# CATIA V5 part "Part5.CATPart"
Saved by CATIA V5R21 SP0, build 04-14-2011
Part number: Part5
Bounding box of the stored display mesh (mm): x 0 to 0, y -30 to 30, z -30 to 30
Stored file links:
  C:\Users\RIAD MAHAMUD PIASH\Desktop\Part5.CATPart
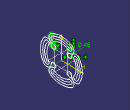
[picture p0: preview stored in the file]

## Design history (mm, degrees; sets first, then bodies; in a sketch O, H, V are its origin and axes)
Body1 (main body)
  Sketch1 on yz-plane, origin (0, 0, 0), H (0, 1, 0), V (0, 0, 1)
    construction circle A1 centre (0, 0) radius 24
    arc A2 centre (0, 0) radius 24 from (12, 20.7846) to (-12, 20.7846) ccw
    point P1 (12, 20.7846)
    arc A3 centre (12, 20.7846) radius 6 from (15, 25.9808) to (13.5233, 14.9812) cw
    arc A4 centre (-12, 20.7846) radius 6 from (-13.1281, 14.8916) to (-15, 25.9808) cw
    arc A5 centre (0, 0) radius 30 from (-15, 25.9808) to (15, 25.9808) cw
    construction arc A6 centre (0, 0) radius 24 from (12, 20.7846) to (-12, 20.7846) ccw
    arc A7 centre (12, 20.7846) radius 3 from (13.5, 23.3827) to (10.5, 18.1865) cw
    arc A8 centre (-12, 20.7846) radius 3 from (-10.5, 18.1865) to (-13.5, 23.3827) cw
    arc A9 centre (0, 0) radius 21 from (10.5, 18.1865) to (-10.5, 18.1865) ccw
    arc A10 centre (0, 0) radius 27 from (-13.5, 23.3827) to (13.5, 23.3827) cw
    construction arc A11 centre (0, 0) radius 24 from (-20.7846, 12) to (-20.7846, -12) ccw
    arc A12 centre (-20.7846, -12) radius 6 from (-14.8916, -13.1281) to (-25.9808, -15) cw
    arc A13 centre (0, 0) radius 30 from (-25.9808, -15) to (-25.9808, 15) cw
    arc A14 centre (-20.7846, 12) radius 6 from (-25.9808, 15) to (-14.9812, 13.5233) cw
    arc A15 centre (0, 0) radius 24 from (-20.7846, 12) to (-20.7846, -12) ccw
    arc A16 centre (-20.7846, 12) radius 3 from (-23.3827, 13.5) to (-18.1865, 10.5) cw
    arc A17 centre (-20.7846, -12) radius 3 from (-18.1865, -10.5) to (-23.3827, -13.5) cw
    arc A18 centre (0, 0) radius 21 from (-18.1865, 10.5) to (-18.1865, -10.5) ccw
    arc A19 centre (0, 0) radius 27 from (-23.3827, -13.5) to (-23.3827, 13.5) cw
    construction arc A20 centre (0, 0) radius 24 from (-12, -20.7846) to (12, -20.7846) ccw
    arc A21 centre (12, -20.7846) radius 6 from (13.1281, -14.8916) to (15, -25.9808) cw
    arc A22 centre (0, 0) radius 30 from (15, -25.9808) to (-15, -25.9808) cw
    arc A23 centre (-12, -20.7846) radius 6 from (-15, -25.9808) to (-13.5233, -14.9812) cw
    arc A24 centre (0, 0) radius 24 from (-12, -20.7846) to (12, -20.7846) ccw
    arc A25 centre (-12, -20.7846) radius 3 from (-13.5, -23.3827) to (-10.5, -18.1865) cw
    arc A26 centre (12, -20.7846) radius 3 from (10.5, -18.1865) to (13.5, -23.3827) cw
    arc A27 centre (0, 0) radius 21 from (-10.5, -18.1865) to (10.5, -18.1865) ccw
    arc A28 centre (0, 0) radius 27 from (13.5, -23.3827) to (-13.5, -23.3827) cw
    construction arc A29 centre (0, 0) radius 24 from (20.7846, -12) to (20.7846, 12) ccw
    arc A30 centre (20.7846, 12) radius 6 from (14.8916, 13.1281) to (25.9808, 15) cw
    arc A31 centre (0, 0) radius 30 from (25.9808, 15) to (25.9808, -15) cw
    arc A32 centre (20.7846, -12) radius 6 from (25.9808, -15) to (14.9812, -13.5233) cw
    arc A33 centre (0, 0) radius 24 from (20.7846, -12) to (20.7846, 12) ccw
    arc A34 centre (20.7846, -12) radius 3 from (23.3827, -13.5) to (18.1865, -10.5) cw
    arc A35 centre (20.7846, 12) radius 3 from (18.1865, 10.5) to (23.3827, 13.5) cw
    arc A36 centre (0, 0) radius 21 from (18.1865, -10.5) to (18.1865, 10.5) ccw
    arc A37 centre (0, 0) radius 27 from (23.3827, 13.5) to (23.3827, -13.5) cw
    construction arc A38 centre (0, 0) radius 24 from (12, 20.7846) to (-12, 20.7846) ccw
    arc A39 centre (-12, 20.7846) radius 6 from (-13.1281, 14.8916) to (-15, 25.9808) cw
    arc A40 centre (0, 0) radius 30 from (-15, 25.9808) to (15, 25.9808) cw
    arc A41 centre (12, 20.7846) radius 6 from (15, 25.9808) to (13.5233, 14.9812) cw
    arc A42 centre (0, 0) radius 24 from (12, 20.7846) to (-12, 20.7846) ccw
    arc A43 centre (12, 20.7846) radius 3 from (13.5, 23.3827) to (10.5, 18.1865) cw
    arc A44 centre (-12, 20.7846) radius 3 from (-10.5, 18.1865) to (-13.5, 23.3827) cw
    arc A45 centre (0, 0) radius 21 from (10.5, 18.1865) to (-10.5, 18.1865) ccw
    arc A46 centre (0, 0) radius 27 from (-13.5, 23.3827) to (13.5, 23.3827) cw
    construction arc A47 centre (0, 0) radius 15.6788 from (-10.0781, 12.0107) to (-12.0107, 10.0781) ccw
    arc A48 centre (-10.0781, 12.0107) radius 2 from (-9.564, 13.9434) to (-8.7926, 10.4786) cw
    arc A49 centre (-12.0107, 10.0781) radius 2 from (-10.4786, 8.7926) to (-13.9632, 9.6451) cw
    arc A50 centre (0, 0) radius 13.6788 from (-8.7926, 10.4786) to (-10.4786, 8.7926) ccw
    construction arc A51 centre (0, 0) radius 15.6788 from (-12.0107, -10.0781) to (-10.0781, -12.0107) ccw
    arc A52 centre (-12.0107, -10.0781) radius 2 from (-13.9434, -9.564) to (-10.4786, -8.7926) cw
    arc A53 centre (-10.0781, -12.0107) radius 2 from (-8.7926, -10.4786) to (-9.6451, -13.9632) cw
    arc A54 centre (0, 0) radius 13.6788 from (-10.4786, -8.7926) to (-8.7926, -10.4786) ccw
    construction arc A55 centre (0, 0) radius 15.6788 from (10.0781, -12.0107) to (12.0107, -10.0781) ccw
    arc A56 centre (10.0781, -12.0107) radius 2 from (9.564, -13.9434) to (8.7926, -10.4786) cw
    arc A57 centre (12.0107, -10.0781) radius 2 from (10.4786, -8.7926) to (13.9632, -9.6451) cw
    arc A58 centre (0, 0) radius 13.6788 from (8.7926, -10.4786) to (10.4786, -8.7926) ccw
    construction arc A59 centre (0, 0) radius 15.6788 from (12.0107, 10.0781) to (10.0781, 12.0107) ccw
    arc A60 centre (12.0107, 10.0781) radius 2 from (13.9434, 9.564) to (10.4786, 8.7926) cw
    arc A61 centre (10.0781, 12.0107) radius 2 from (8.7926, 10.4786) to (9.6451, 13.9632) cw
    arc A62 centre (0, 0) radius 13.6788 from (10.4786, 8.7926) to (8.7926, 10.4786) ccw
    construction arc A63 centre (0, 0) radius 15.6788 from (-10.0781, 12.0107) to (-12.0107, 10.0781) ccw
    arc A64 centre (-10.0781, 12.0107) radius 2 from (-9.564, 13.9434) to (-8.7926, 10.4786) cw
    arc A65 centre (-12.0107, 10.0781) radius 2 from (-10.4786, 8.7926) to (-13.9632, 9.6451) cw
    arc A66 centre (0, 0) radius 13.6788 from (-8.7926, 10.4786) to (-10.4786, 8.7926) ccw
    line L1 (-13.9632, 9.6451) -> (-14.9812, 13.5233)
    line L2 (-13.1281, 14.8916) -> (-9.564, 13.9434)
    point P71 (-13.1281, 14.8916)
    line L3 (-9.6451, -13.9632) -> (-13.5233, -14.9812)
    line L4 (-14.8916, -13.1281) -> (-13.9434, -9.564)
    line L5 (13.9632, -9.6451) -> (14.9812, -13.5233)
    line L6 (13.1281, -14.8916) -> (9.564, -13.9434)
    line L7 (9.6451, 13.9632) -> (13.5233, 14.9812)
    line L8 (14.8916, 13.1281) -> (13.9434, 9.564)
    line L9 (-13.9632, 9.6451) -> (-14.9812, 13.5233)
    line L10 (-13.1281, 14.8916) -> (-9.564, 13.9434)
    radius A1 = 24
    radius A4 = 6
    radius A8 = 3
    radius A49 = 2
    coincidence: P1 A1, P71 A4
    tangency: A4 A5, A5 A3, A9 A8, A8 A10, A10 A7, A7 A9, A50 A49, A48 A50, L1 A14, L2 A48
    concentricity: A5 O, A9 O, A10 O, A50 O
